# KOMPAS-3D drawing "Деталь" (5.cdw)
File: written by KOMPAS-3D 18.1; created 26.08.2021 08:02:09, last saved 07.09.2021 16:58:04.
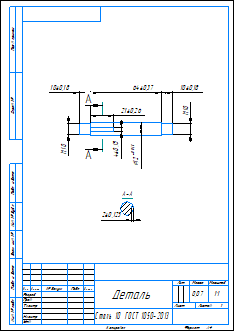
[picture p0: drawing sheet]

Sheet 1: A4, portrait

Document properties: Автор: 111; Масса: 0.0680655

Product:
- Part/product: Деталь
    Масса: 0.0680655
  - Body: Тело 4
      Масса: 0.0556636
  - Body: Тело 5
      Масса: 0.00617009
  - Body: Тело 6
      Масса: 0.00623179

Title block, sheet 1: Наименование: Деталь; Материал: Сталь 10  ГОСТ 1050-2013; Масса: 0,07; Количество листов документа: 1; Форматы листов документа: A4; stored path: C:\Users\admin\Desktop\ffb\5.cdw

Views: Вид 1, Сверху
Referenced files in C:\Users\admin\Desktop\ffb\: 10.m3d
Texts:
  Стили документа
Dimensions and other numbers on the sheet: 12; 10±0,18; 64±0,37; 4±0,15; 21±0,26; 2; 1:1; 1; 0,07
